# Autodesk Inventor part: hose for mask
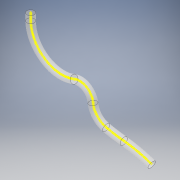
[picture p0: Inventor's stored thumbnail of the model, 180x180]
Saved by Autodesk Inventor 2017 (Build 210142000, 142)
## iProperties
Created: 2020-03
Part Number: hose for mask
Material: Polycarbonate, Clear
Document SubType Name: Modeling
Designer: user
Density: 1.2 g/cm^3
Appearance: Polycarbonate - Clear
Author: user
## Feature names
1. Rectangular Pattern1
2. Sweep2
## Parameters: d1 = 25 mm, d2 = 25.4 mm, d7 = 3.16094 mm, d8 = 0.3 mm, d9 = 0, d10 = 0
